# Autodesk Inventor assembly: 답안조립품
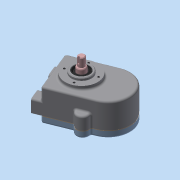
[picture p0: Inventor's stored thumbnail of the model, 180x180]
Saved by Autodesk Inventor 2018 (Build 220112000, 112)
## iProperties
Created: 2024-03
Part Number: 답안조립품
Material: 일반
Document SubType Name: Assembly
Designer: home
Author: home
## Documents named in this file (9)
- C:\Users\home\Desktop\740304V1021\답안조립품.iam
- C:\Users\home\Desktop\740304V1021\본체.ipt
- C:\Users\home\Desktop\740304V1021\가스켓.ipt
- C:\Users\home\Desktop\740304V1021\구동기어.ipt
- C:\Users\home\Desktop\740304V1021\스퍼기어.ipt
- C:\Users\home\Desktop\740304V1021\오일 실 14 25 7.ipt
- C:\Users\home\Desktop\740304V1021\오일레스 부시.ipt
- C:\Users\home\Desktop\740304V1021\육각 소켓 머리 볼트 M5x12.ipt
- C:\Users\home\Desktop\740304V1021\커버.ipt
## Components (2 placed, 2 different names)
1. 가스켓:1
2. 구동기어:1
